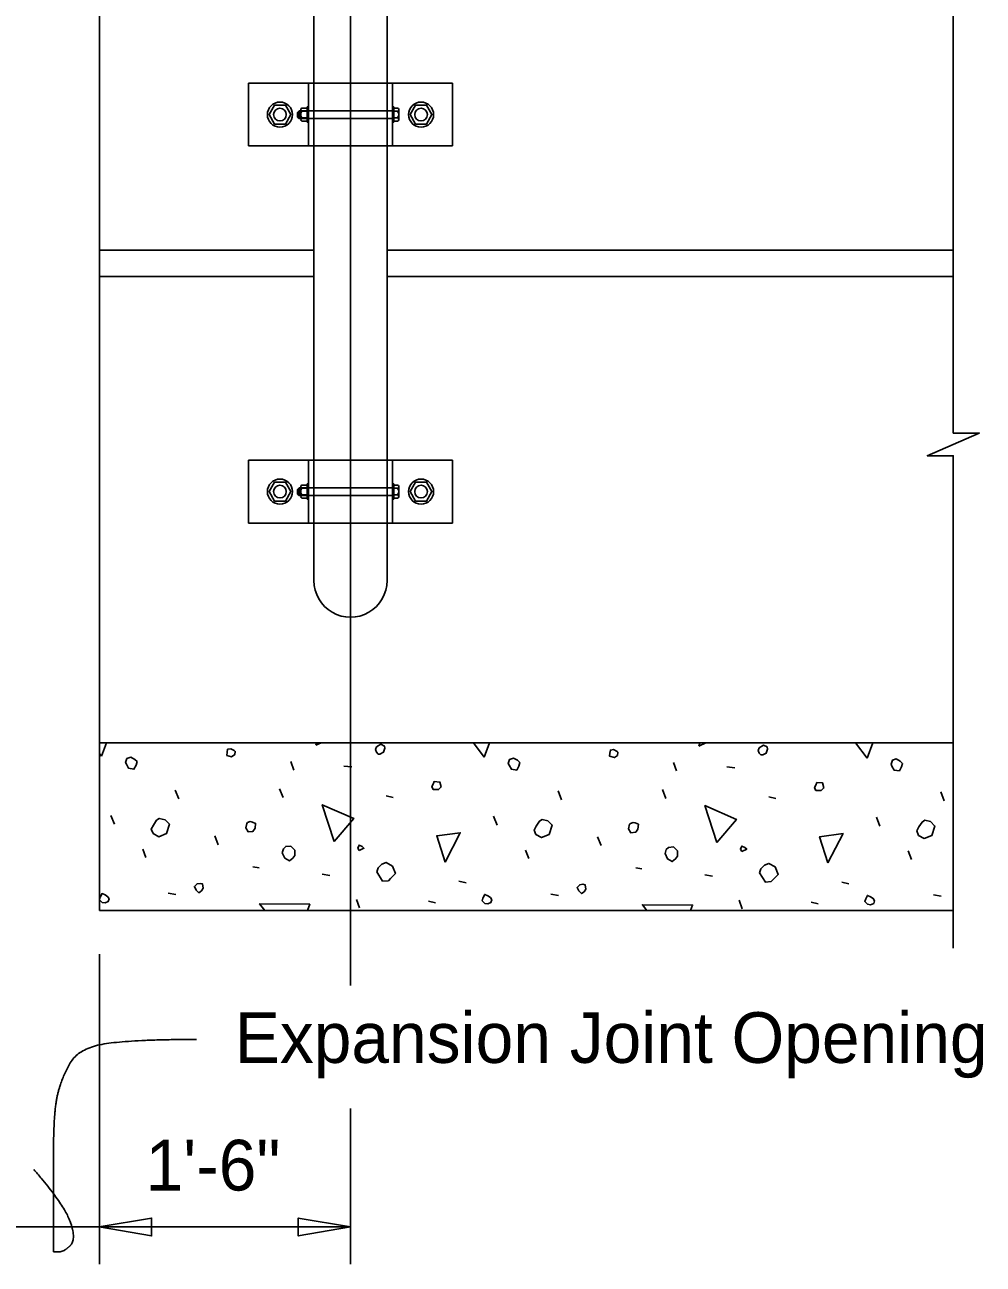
# Model space of a CAD drawing. Extents: x 0 to 41.1, y 0 to 26.4.
# Drawn here: x 27.279 to 31.095, y 12.395 to 17.327 of the extents above; entities that cross this region are included whole.
import ezdxf

# ---------------------------------------------------------------- set-up
doc = ezdxf.new("R2010")
doc.units = 0
for name, color, linetype in [('CL_Major', 7, 'Continuous'), ('Dimension', 7, 'Continuous'), ('Miscellaneous', 7, 'Continuous'), ('SteelMisc', 7, 'Continuous'), ('SteelMisc_h', 7, 'Continuous'), ('SupstrConc', 7, 'Continuous'), ('TextStructures', 7, 'Continuous')]:
    doc.layers.add(name, color=color, linetype=linetype)

msp = doc.modelspace()

# ---------------------------------------------------------------- linework, layer by layer
at = {"layer": 'CL_Major'}
for p, q in [((28.5763, 25.6784), (28.5763, 13.5039)), ((28.5763, 13.0148), (28.5763, 12.3953))]:
    msp.add_line(p, q, dxfattribs=at)
at = {"layer": 'Dimension'}
for p, q in [((27.5763, 13.6294), (27.5763, 12.3953)), ((28.5763, 12.5434), (26.2429, 12.5434))]:
    msp.add_line(p, q, dxfattribs=at)
for points in [[(30.9762, 20.1983), (30.9762, 19.1806), (31.0795, 19.1806), (30.9762, 19.1356), (30.8729, 19.0906), (30.9762, 19.0906), (30.9762, 17.1361)], [(30.9761, 17.1361), (30.9761, 15.7022), (31.0795, 15.7022), (30.9761, 15.6572), (30.8728, 15.6122), (30.9761, 15.6122), (30.9761, 13.653)]]:
    msp.add_lwpolyline(points, dxfattribs=at)
for points in [[(27.5762, 12.5434), (27.7845, 12.5081), (27.7845, 12.5787)], [(28.5762, 12.5434), (28.368, 12.5787), (28.368, 12.5081)]]:
    msp.add_lwpolyline(points, close=True, dxfattribs=at)
msp.add_open_spline([(27.3159, 12.7718), (27.434, 12.6355), (27.4854, 12.4962), (27.437, 12.4448), (27.3939, 12.4448), (27.3939, 12.4448), (27.3939, 12.6961), (27.3939, 12.9989), (27.4249, 13.1352), (27.4975, 13.2594), (27.7306, 13.2896), (27.9637, 13.2896)], degree=2, dxfattribs=at)
at = {"layer": 'Miscellaneous'}
for p, q in [((28.3687, 16.9625), (28.3687, 16.9746)), ((28.3744, 16.9625), (28.3744, 16.9746)), ((28.3687, 15.4625), (28.3687, 15.4746)), ((28.3744, 15.4625), (28.3744, 15.4746)), ((29.525, 14.4695), (29.5261, 14.4692)), ((28.3505, 14.3614), (28.3382, 14.395)), ((28.5503, 14.3773), (28.5821, 14.3738)), ((29.8743, 14.3579), (29.862, 14.3915)), ((30.0741, 14.3738), (30.1059, 14.3702)), ((27.8927, 14.2465), (27.8785, 14.2819)), ((28.3081, 14.2518), (28.294, 14.2872)), ((28.7182, 14.2589), (28.7465, 14.2518)), ((29.4165, 14.243), (29.4024, 14.2783)), ((29.8319, 14.2483), (29.8178, 14.2836)), ((30.242, 14.2553), (30.2703, 14.2483)), ((30.9403, 14.2394), (30.9262, 14.2748)), ((27.6364, 14.1457), (27.6222, 14.1811)), ((29.1602, 14.1422), (29.146, 14.1776)), ((30.684, 14.1387), (30.6698, 14.174)), ((28.05, 14.0644), (28.0359, 14.0998)), ((29.5738, 14.0609), (29.5597, 14.0962)), ((27.7619, 14.0131), (27.7495, 14.0467)), ((29.2857, 14.0096), (29.2733, 14.0432)), ((30.8095, 14.0061), (30.7971, 14.0397)), ((28.1879, 13.976), (28.2126, 13.9725)), ((29.7117, 13.9725), (29.7365, 13.969)), ((28.4637, 13.9477), (28.4937, 13.9424)), ((29.0081, 13.9195), (29.0364, 13.9124)), ((29.9875, 13.9442), (30.0175, 13.9389)), ((30.532, 13.9159), (30.5602, 13.9089)), ((27.8503, 13.8717), (27.8803, 13.8664)), ((29.3741, 13.8682), (29.4041, 13.8629)), ((30.8979, 13.8647), (30.9279, 13.8594)), ((28.6122, 13.8134), (28.5998, 13.847)), ((28.8862, 13.8399), (28.9145, 13.8328)), ((30.136, 13.8099), (30.1236, 13.8434)), ((30.41, 13.8364), (30.4383, 13.8293))]:
    msp.add_line(p, q, dxfattribs=at)
for points in [[(27.605, 14.4695), (27.5851, 14.4162)], [(28.4389, 14.4604), (28.4417, 14.4695)], [(28.4591, 14.4695), (28.4389, 14.4604)], [(28.6864, 14.425), (28.6935, 14.425), (28.7076, 14.4321), (28.7129, 14.448), (28.7112, 14.4569), (28.697, 14.4639), (28.6793, 14.4533), (28.6758, 14.4427), (28.6793, 14.4321), (28.6864, 14.425)], [(29.1089, 14.4127), (29.0657, 14.4695)], [(29.1301, 14.4695), (29.1089, 14.4127)], [(29.9627, 14.4569), (29.9666, 14.4695)], [(29.9908, 14.4695), (29.9627, 14.4569)], [(30.2102, 14.4215), (30.2173, 14.4215), (30.2314, 14.4286), (30.2367, 14.4445), (30.235, 14.4533), (30.2208, 14.4604), (30.2032, 14.4498), (30.1996, 14.4392), (30.2032, 14.4286), (30.2102, 14.4215)], [(30.6327, 14.4091), (30.5869, 14.4695)], [(30.6553, 14.4695), (30.6327, 14.4091)], [(27.5851, 14.4162), (27.5763, 14.4278)], [(27.6841, 14.3844), (27.6929, 14.3685), (27.7141, 14.3649), (27.723, 14.3808), (27.7265, 14.395), (27.7177, 14.4038), (27.7018, 14.4127), (27.6859, 14.4074), (27.6805, 14.3915), (27.6841, 14.3844)], [(28.0836, 14.4197), (28.103, 14.4144), (28.1154, 14.4233), (28.1172, 14.4356), (28.1137, 14.4392), (28.0995, 14.4463), (28.0871, 14.4445), (28.0854, 14.4321), (28.0836, 14.4197)], [(29.2079, 14.3808), (29.2167, 14.3649), (29.238, 14.3614), (29.2468, 14.3773), (29.2503, 14.3915), (29.2415, 14.4003), (29.2256, 14.4091), (29.2097, 14.4038), (29.2044, 14.3879), (29.2079, 14.3808)], [(29.6074, 14.4162), (29.6269, 14.4109), (29.6392, 14.4197), (29.641, 14.4321), (29.6375, 14.4356), (29.6233, 14.4427), (29.611, 14.4409), (29.6092, 14.4286), (29.6074, 14.4162)], [(30.7317, 14.3773), (30.7406, 14.3614), (30.7618, 14.3579), (30.7706, 14.3738), (30.7741, 14.3879), (30.7653, 14.3968), (30.7494, 14.4056), (30.7335, 14.4003), (30.7282, 14.3844), (30.7317, 14.3773)], [(28.9056, 14.2836), (28.9268, 14.2836), (28.9374, 14.2942), (28.9321, 14.3137), (28.9091, 14.3154), (28.9056, 14.3048), (28.9003, 14.296), (28.9056, 14.2836), (28.9021, 14.2872)], [(30.4294, 14.2801), (30.4506, 14.2801), (30.4612, 14.2907), (30.4559, 14.3101), (30.433, 14.3119), (30.4294, 14.3013), (30.4241, 14.2925), (30.4294, 14.2801), (30.4259, 14.2836)], [(28.5114, 14.0768), (28.4637, 14.2235), (28.5892, 14.1687), (28.5114, 14.0768)], [(30.0352, 14.0733), (29.9875, 14.22), (30.113, 14.1652), (30.0352, 14.0733)], [(27.7902, 14.1086), (27.8131, 14.0962), (27.8432, 14.1086), (27.8556, 14.1457), (27.8379, 14.1634), (27.8149, 14.1687), (27.8043, 14.1616), (27.7919, 14.1422), (27.7831, 14.1263), (27.7902, 14.1086)], [(28.1596, 14.1316), (28.1685, 14.1157), (28.1879, 14.1174), (28.1967, 14.1298), (28.1985, 14.1493), (28.1861, 14.1546), (28.1773, 14.1563), (28.1667, 14.1528), (28.1631, 14.1493), (28.1596, 14.1316)], [(29.314, 14.1051), (29.3369, 14.0927), (29.367, 14.1051), (29.3794, 14.1422), (29.3617, 14.1599), (29.3387, 14.1652), (29.3281, 14.1581), (29.3157, 14.1387), (29.3069, 14.1228), (29.314, 14.1051)], [(30.8378, 14.1015), (30.8608, 14.0892), (30.8908, 14.1015), (30.9032, 14.1387), (30.8855, 14.1563), (30.8625, 14.1616), (30.8519, 14.1546), (30.8395, 14.1351), (30.8307, 14.1192), (30.8378, 14.1015)], [(28.9533, 13.9955), (28.9198, 14.0998), (29.0134, 14.1121), (28.9533, 13.9955)], [(29.6834, 14.1281), (29.6923, 14.1121), (29.7117, 14.1139), (29.7206, 14.1263), (29.7223, 14.1457), (29.7099, 14.151), (29.7011, 14.1528), (29.6905, 14.1493), (29.687, 14.1457), (29.6834, 14.1281)], [(30.4772, 13.9919), (30.4436, 14.0962), (30.5373, 14.1086), (30.4772, 13.9919)], [(28.3046, 14.0326), (28.3152, 14.0114), (28.3329, 14.0008), (28.347, 14.0114), (28.3541, 14.022), (28.3541, 14.0432), (28.3382, 14.0591), (28.3187, 14.0573), (28.3099, 14.0485), (28.3046, 14.0326)], [(28.6104, 14.0414), (28.6298, 14.0503), (28.6228, 14.0573), (28.6104, 14.0626), (28.6051, 14.0503), (28.6104, 14.0414)], [(29.8284, 14.0291), (29.839, 14.0078), (29.8567, 13.9972), (29.8708, 14.0078), (29.8779, 14.0185), (29.8779, 14.0397), (29.862, 14.0556), (29.8425, 14.0538), (29.8337, 14.045), (29.8284, 14.0291)], [(30.1342, 14.0379), (30.1537, 14.0467), (30.1466, 14.0538), (30.1342, 14.0591), (30.1289, 14.0467), (30.1342, 14.0379)], [(28.6811, 13.9566), (28.7041, 13.9195), (28.7271, 13.9212), (28.7359, 13.9301), (28.7554, 13.9495), (28.743, 13.9796), (28.7182, 13.9937), (28.7006, 13.9866), (28.6864, 13.9725), (28.6811, 13.9566)], [(30.2049, 13.953), (30.2279, 13.9159), (30.2509, 13.9177), (30.2597, 13.9265), (30.2792, 13.946), (30.2668, 13.976), (30.242, 13.9902), (30.2244, 13.9831), (30.2102, 13.969), (30.2049, 13.953)], [(27.9616, 13.8841), (27.9722, 13.8735), (27.9828, 13.8806), (27.9899, 13.8912), (27.9864, 13.9089), (27.9775, 13.9106), (27.9652, 13.9089), (27.9546, 13.8982), (27.9616, 13.8841)], [(29.4854, 13.8806), (29.496, 13.87), (29.5067, 13.877), (29.5137, 13.8876), (29.5102, 13.9053), (29.5013, 13.9071), (29.489, 13.9053), (29.4784, 13.8947), (29.4854, 13.8806)], [(27.5869, 13.8346), (27.5992, 13.8328), (27.6116, 13.8381), (27.6151, 13.8487), (27.6098, 13.8576), (27.5992, 13.8647), (27.5869, 13.87), (27.5798, 13.8558), (27.5763, 13.8452), (27.5869, 13.8346)], [(29.1107, 13.8311), (29.123, 13.8293), (29.1354, 13.8346), (29.139, 13.8452), (29.1337, 13.8541), (29.123, 13.8611), (29.1107, 13.8664), (29.1036, 13.8523), (29.1001, 13.8417), (29.1107, 13.8311)], [(30.6345, 13.8275), (30.6469, 13.8258), (30.6592, 13.8311), (30.6628, 13.8417), (30.6575, 13.8505), (30.6469, 13.8576), (30.6345, 13.8629), (30.6274, 13.8487), (30.6239, 13.8381), (30.6345, 13.8275)], [(28.2346, 13.8028), (28.2144, 13.8293), (28.4142, 13.8275), (28.4049, 13.8028)], [(29.7557, 13.8028), (29.7382, 13.8258), (29.938, 13.824), (29.9301, 13.8028)]]:
    msp.add_lwpolyline(points, dxfattribs=at)
at = {"layer": 'SteelMisc'}
for p, q in [((28.4305, 17.0944), (28.4305, 17.6079)), ((28.7221, 17.0944), (28.7221, 17.6079)), ((28.1703, 17.0944), (28.9823, 17.0944)), ((28.1703, 16.8444), (28.1703, 17.0944)), ((28.4096, 17.0944), (28.4096, 16.8444)), ((28.743, 17.0944), (28.743, 16.8444)), ((28.9823, 17.0944), (28.9823, 16.8444)), ((28.3659, 16.9774), (28.3715, 16.984)), ((28.3659, 16.9597), (28.3659, 16.9774)), ((28.3715, 16.984), (28.3781, 16.984)), ((28.3715, 16.9541), (28.3715, 16.984)), ((28.3781, 16.9873), (28.3781, 16.9516)), ((28.3828, 16.9824), (28.4031, 16.9824)), ((28.383, 16.9954), (28.4031, 16.9954)), ((28.4031, 16.9997), (28.4031, 16.9391)), ((28.4031, 16.9997), (28.4096, 16.9997)), ((28.4031, 16.9954), (28.4031, 16.9435)), ((28.7492, 16.9997), (28.7432, 16.9997)), ((28.7492, 16.9997), (28.7492, 16.9391)), ((28.7639, 16.9954), (28.7492, 16.9954)), ((28.7641, 16.9824), (28.7492, 16.9824)), ((28.769, 16.95), (28.769, 16.9889)), ((28.3659, 16.9597), (28.3715, 16.9541)), ((28.3715, 16.9541), (28.3781, 16.9541)), ((28.3828, 16.9565), (28.4031, 16.9565)), ((28.3831, 16.9435), (28.4031, 16.9435)), ((28.4031, 16.9391), (28.4096, 16.9391)), ((28.7492, 16.9391), (28.7432, 16.9391)), ((28.7641, 16.9564), (28.7492, 16.9564)), ((28.7639, 16.9434), (28.7492, 16.9434)), ((28.9823, 16.8444), (28.1703, 16.8444)), ((28.4305, 16.8444), (28.4305, 15.5944)), ((28.7221, 16.8444), (28.7221, 15.5944)), ((28.1703, 15.5944), (28.9823, 15.5944)), ((28.1703, 15.3444), (28.1703, 15.5944)), ((28.4096, 15.5944), (28.4096, 15.3444)), ((28.743, 15.5944), (28.743, 15.3444)), ((28.9823, 15.5944), (28.9823, 15.3444)), ((28.3781, 15.4873), (28.3781, 15.4516)), ((28.383, 15.4954), (28.4031, 15.4954)), ((28.4031, 15.4997), (28.4031, 15.4391)), ((28.4031, 15.4997), (28.4096, 15.4997)), ((28.4031, 15.4954), (28.4031, 15.4435)), ((28.7492, 15.4997), (28.7432, 15.4997)), ((28.7492, 15.4997), (28.7492, 15.4391)), ((28.7639, 15.4954), (28.7492, 15.4954)), ((28.769, 15.45), (28.769, 15.4889)), ((28.3659, 15.4774), (28.3715, 15.484)), ((28.3659, 15.4597), (28.3659, 15.4774)), ((28.3659, 15.4597), (28.3715, 15.4541)), ((28.3715, 15.484), (28.3781, 15.484)), ((28.3715, 15.4541), (28.3715, 15.484)), ((28.3715, 15.4541), (28.3781, 15.4541)), ((28.3828, 15.4824), (28.4031, 15.4824)), ((28.3828, 15.4565), (28.4031, 15.4565)), ((28.3831, 15.4435), (28.4031, 15.4435)), ((28.4031, 15.4391), (28.4096, 15.4391)), ((28.7492, 15.4391), (28.7432, 15.4391)), ((28.7641, 15.4824), (28.7492, 15.4824)), ((28.7641, 15.4564), (28.7492, 15.4564)), ((28.7639, 15.4434), (28.7492, 15.4434)), ((28.9823, 15.3444), (28.1703, 15.3444)), ((28.4303, 15.3444), (28.4303, 15.1153)), ((28.722, 15.1153), (28.722, 15.3444))]:
    msp.add_line(p, q, dxfattribs=at)
for points in [[(28.2736, 17.007), (28.317, 17.007), (28.3386, 16.9694), (28.317, 16.9319), (28.2736, 16.9319), (28.252, 16.9694)], [(28.8356, 17.007), (28.8789, 17.007), (28.9006, 16.9694), (28.8789, 16.9319), (28.8356, 16.9319), (28.8139, 16.9694)], [(28.2736, 15.507), (28.317, 15.507), (28.3386, 15.4694), (28.317, 15.4319), (28.2736, 15.4319), (28.252, 15.4694)], [(28.8356, 15.507), (28.8789, 15.507), (28.9006, 15.4694), (28.8789, 15.4319), (28.8356, 15.4319), (28.8139, 15.4694)]]:
    msp.add_lwpolyline(points, close=True, dxfattribs=at)
for centre, radius in [((28.2953, 16.9694), 0.05), ((28.8573, 16.9694), 0.05), ((28.2953, 16.9694), 0.025), ((28.8573, 16.9694), 0.025), ((28.2953, 15.4694), 0.05), ((28.2953, 15.4694), 0.025), ((28.8573, 15.4694), 0.05), ((28.8573, 15.4694), 0.025)]:
    msp.add_circle(centre, radius, dxfattribs=at)
for centre, radius, start, end in [((28.3846, 16.9889), 0.00674, 104.4891, 254.1889), ((28.3975, 16.9694), 0.0196, 138.628, 221.372), ((28.7622, 16.9889), 0.00673, 285.7823, 75.5404), ((28.7493, 16.9694), 0.0196, 318.628, 41.372), ((28.3846, 16.95), 0.00673, 105.7823, 255.5404), ((28.7622, 16.95), 0.00674, 284.4891, 74.1889), ((28.3846, 15.4889), 0.00674, 104.4891, 254.1889), ((28.7622, 15.4889), 0.00673, 285.7823, 75.5404), ((28.3975, 15.4694), 0.0196, 138.628, 221.372), ((28.3846, 15.45), 0.00673, 105.7823, 255.5404), ((28.7622, 15.45), 0.00674, 284.4891, 74.1889), ((28.7493, 15.4694), 0.0196, 318.628, 41.372)]:
    msp.add_arc(centre, radius, start, end, dxfattribs=at)
msp.add_ellipse((28.5763, 15.1153), major_axis=(0, 0.1458), ratio=0.999499, start_param=1.570796, end_param=4.712389, dxfattribs=at)
at = {"layer": 'SteelMisc_h'}
for p, q in [((28.4305, 17.0944), (28.4305, 16.8444)), ((28.7221, 17.0944), (28.7221, 16.8444)), ((28.743, 16.984), (28.3781, 16.984)), ((28.3781, 16.9541), (28.743, 16.9541)), ((28.4305, 15.5944), (28.4305, 15.3444)), ((28.7221, 15.5944), (28.7221, 15.3444)), ((28.743, 15.484), (28.3781, 15.484)), ((28.3781, 15.4541), (28.743, 15.4541))]:
    msp.add_line(p, q, dxfattribs=at)
at = {"layer": 'SupstrConc'}
for p, q in [((27.5763, 17.4693), (27.5763, 13.8028)), ((27.5763, 16.4295), (28.4305, 16.4295)), ((28.7221, 16.4295), (30.976, 16.4295)), ((27.5763, 16.3254), (28.4305, 16.3254)), ((28.7221, 16.3254), (30.976, 16.3254)), ((27.5763, 14.4695), (30.9761, 14.4695)), ((27.5763, 13.8028), (30.9761, 13.8028))]:
    msp.add_line(p, q, dxfattribs=at)

# ---------------------------------------------------------------- texts
at = {"layer": 'TextStructures'}
for s, p in [('Expansion Joint Opening', (28.1153, 13.1963)), ('1\'-6"', (27.7605, 12.6886))]:
    msp.add_text(s, height=0.2016, dxfattribs=at).set_placement(p)

doc.saveas('drawing.dxf')
